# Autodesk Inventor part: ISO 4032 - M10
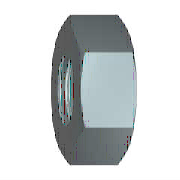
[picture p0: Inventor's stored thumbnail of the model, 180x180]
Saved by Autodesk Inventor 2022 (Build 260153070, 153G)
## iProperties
Created: 2021-02
Part Number: ISO 4032 - M10
Material: Acier inoxydable 440C
Description: Ecrous hexagonaux, style 1 - Produit de classes A et B
Document SubType Name: Modeling
Standard: ISO 4032
Designer: Fabian
Standard Revision: Fourth edition 2012-12-15
Standards Organization: ISO
Language: fr-FR
Size Designation: M10
Categories: <MemberInstance><Categories><Category DisplayName="Visserie" InternalName="e4da775c-781d-43d5-af7c-5136215cf5a6" Mnemonic="FSTN"><Category DisplayName="Ecrous"
Density: 7.75 g/cm^3
Appearance: Semi-poli
IsCustomPart: 0
Author: Fabian
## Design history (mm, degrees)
sketch "Esquisse1"
  geometry: L1 (-9.238, 0)-(-4.619, 8); L2 (-4.619, 8)-(4.619, 8); L3 (4.619, 8)-(9.238, 0); L4 (9.238, 0)-(4.619, -8); L5 (4.619, -8)-(-4.619, -8); L6 (-4.619, -8)-(-9.238, 0); 2 further points
  constraints: 12 end point, 1 coincident, 1 horizontal, 11 other
  dimensions: "d0" = 18.47521 distance of L3.end L1.start (= 1.1547 x SW)
extrude "Corps" new body sketch "Esquisse1" distance "d1" = 8.4 (= KOH); taper "d2" = 0 deg
sketch "Esquisse2"
  geometry: L1 (0, 4.619)-(0, 9.238) reference; L2 (0, 9.238)-(8.4, 9.238) reference; L3 (8.4, 4.619)-(8.4, 9.238) reference; L4 (-1.68, 0)-(10.08, 0) reference; L5 (1.119, 9.238)-(0, 7.3); L6 (7.281, 9.238)-(8.4, 7.3)
  constraints: 4 end point, 4 point on line
  dimensions: "d3" = 30 deg angle of L1 L5 (= ANG1); "d4" = 30 deg angle of L3 L6 (= ANG2); "d5" = 14.6 diameter of L5.end L4 (= SW0); "d6" = 14.6 diameter of L6.end L4 (= SW01)
revolve "Chanfrein1" sketch "Esquisse2" stored, may be unused: angle "d7" = 90 deg
sketch "Esquisse3"
  geometry: 4 further points
  constraints: 1 coincident, 1 other
hole "Filetage" sketch "Esquisse3" at (0, 0) diameter "d25" = 8.376; stored, may be unused: countersink angle "d29" = 82 deg, drill point angle "d31" = 118 deg; dims "d26" = 6, "d27" = 4, "d28" = 2, "d30" = 8
workaxis "Work Axis1"
workplane "Work Plane1"
body "Solid1"
chamfer "Chanfrein2" distance "d8" = 0.8119 (= -0.5 x GD1 + 0.5 x NND); stored, may be unused: angle "d9" = 30 deg, second distance "d40" = 0.8119 (= -0.5 x GD1 + 0.5 x NND)
chamfer "Chanfrein3" distance "d10" = 0.8119 (= -0.5 x GD1 + 0.5 x NND); stored, may be unused: angle "d11" = 30 deg, second distance "d41" = 0.8119 (= -0.5 x GD1 + 0.5 x NND)
other parameters: "ANG1" = 30 deg [user parameter; used in 1 equation term], "ANG2" = 30 deg [user parameter; used in 1 equation term], "KOH" = 8.4 [user parameter; used in 1 equation term], "SW" = 16 [user parameter; used in 2 equation terms], "SW0" = 14.6 [user parameter; used in 2 equation terms], "SW01" = 14.6 (= SW0) [user parameter; used in 1 equation term], "GD1" = 8.3762 (computed from THREADDIA, PTC, TOA) [user parameter; used in 4 equation terms], "d13" = 0, "d14" = 0, "d39" = 0, "d42" = 0, "GUL" = 0.8119 (= 0.541266 x PTC) [user parameter], "TPU" = 6.66667 (computed from PTC) [user parameter], "TOA" = 30 deg [user parameter; used in 1 equation term], "PTC" = 1.5 [user parameter; used in 4 equation terms], "E0" = 18.48 (= 1.155 x SW) [user parameter], "GAL" = 0.8119 (= 0.541266 x PTC) [user parameter]
